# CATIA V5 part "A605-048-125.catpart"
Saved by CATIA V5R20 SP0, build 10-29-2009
Part number: A605-048-125
Source: Unknown
Property "A": "0.000"
Property "ARTICLENO": "A605-048-125"
Property "BOMINFO": "A605-048-125"
Property "CODE": "A605-048-125"
Property "D": "9.000"
Property "FORM": "A"
Property "L": "125.000"
Property "L1": "95.000"
Property "LINA": "A605-048-125"
Property "NB": "A605-048-125"
Property "NBSYN": "$CODE."
Property "NN": "A605"
Property "NT": "Wear Plates, self-lubricating"
Property "SCREW": "2*M8X16"
Property "SUPPLIER": "CF"
Property "W": "48.000"
Bounding box of the stored display mesh (mm): x -48 to 0, y 0 to 5, z -125 to 0
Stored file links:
  C:\Users\Utente\Desktop\3D files A605\A605-048-125.catpart
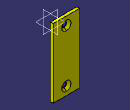
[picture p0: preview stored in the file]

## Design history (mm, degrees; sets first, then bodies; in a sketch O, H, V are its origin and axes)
Body1 "Geometry.1" (main body)
  Solid1 "A605-048-125.catpart": solid without history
